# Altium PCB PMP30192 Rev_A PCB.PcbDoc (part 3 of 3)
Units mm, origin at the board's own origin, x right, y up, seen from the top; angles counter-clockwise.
Board outline 142.24 x 157.48 mm, 4 copper layers (Top Layer, Signal Layer 1, Signal Layer 2, Bottom Layer), stack 1.647 mm thick; 198 components, 99 nets, 479 pads, 192 vias.
Unrouted connection lines stored in the file: 2.
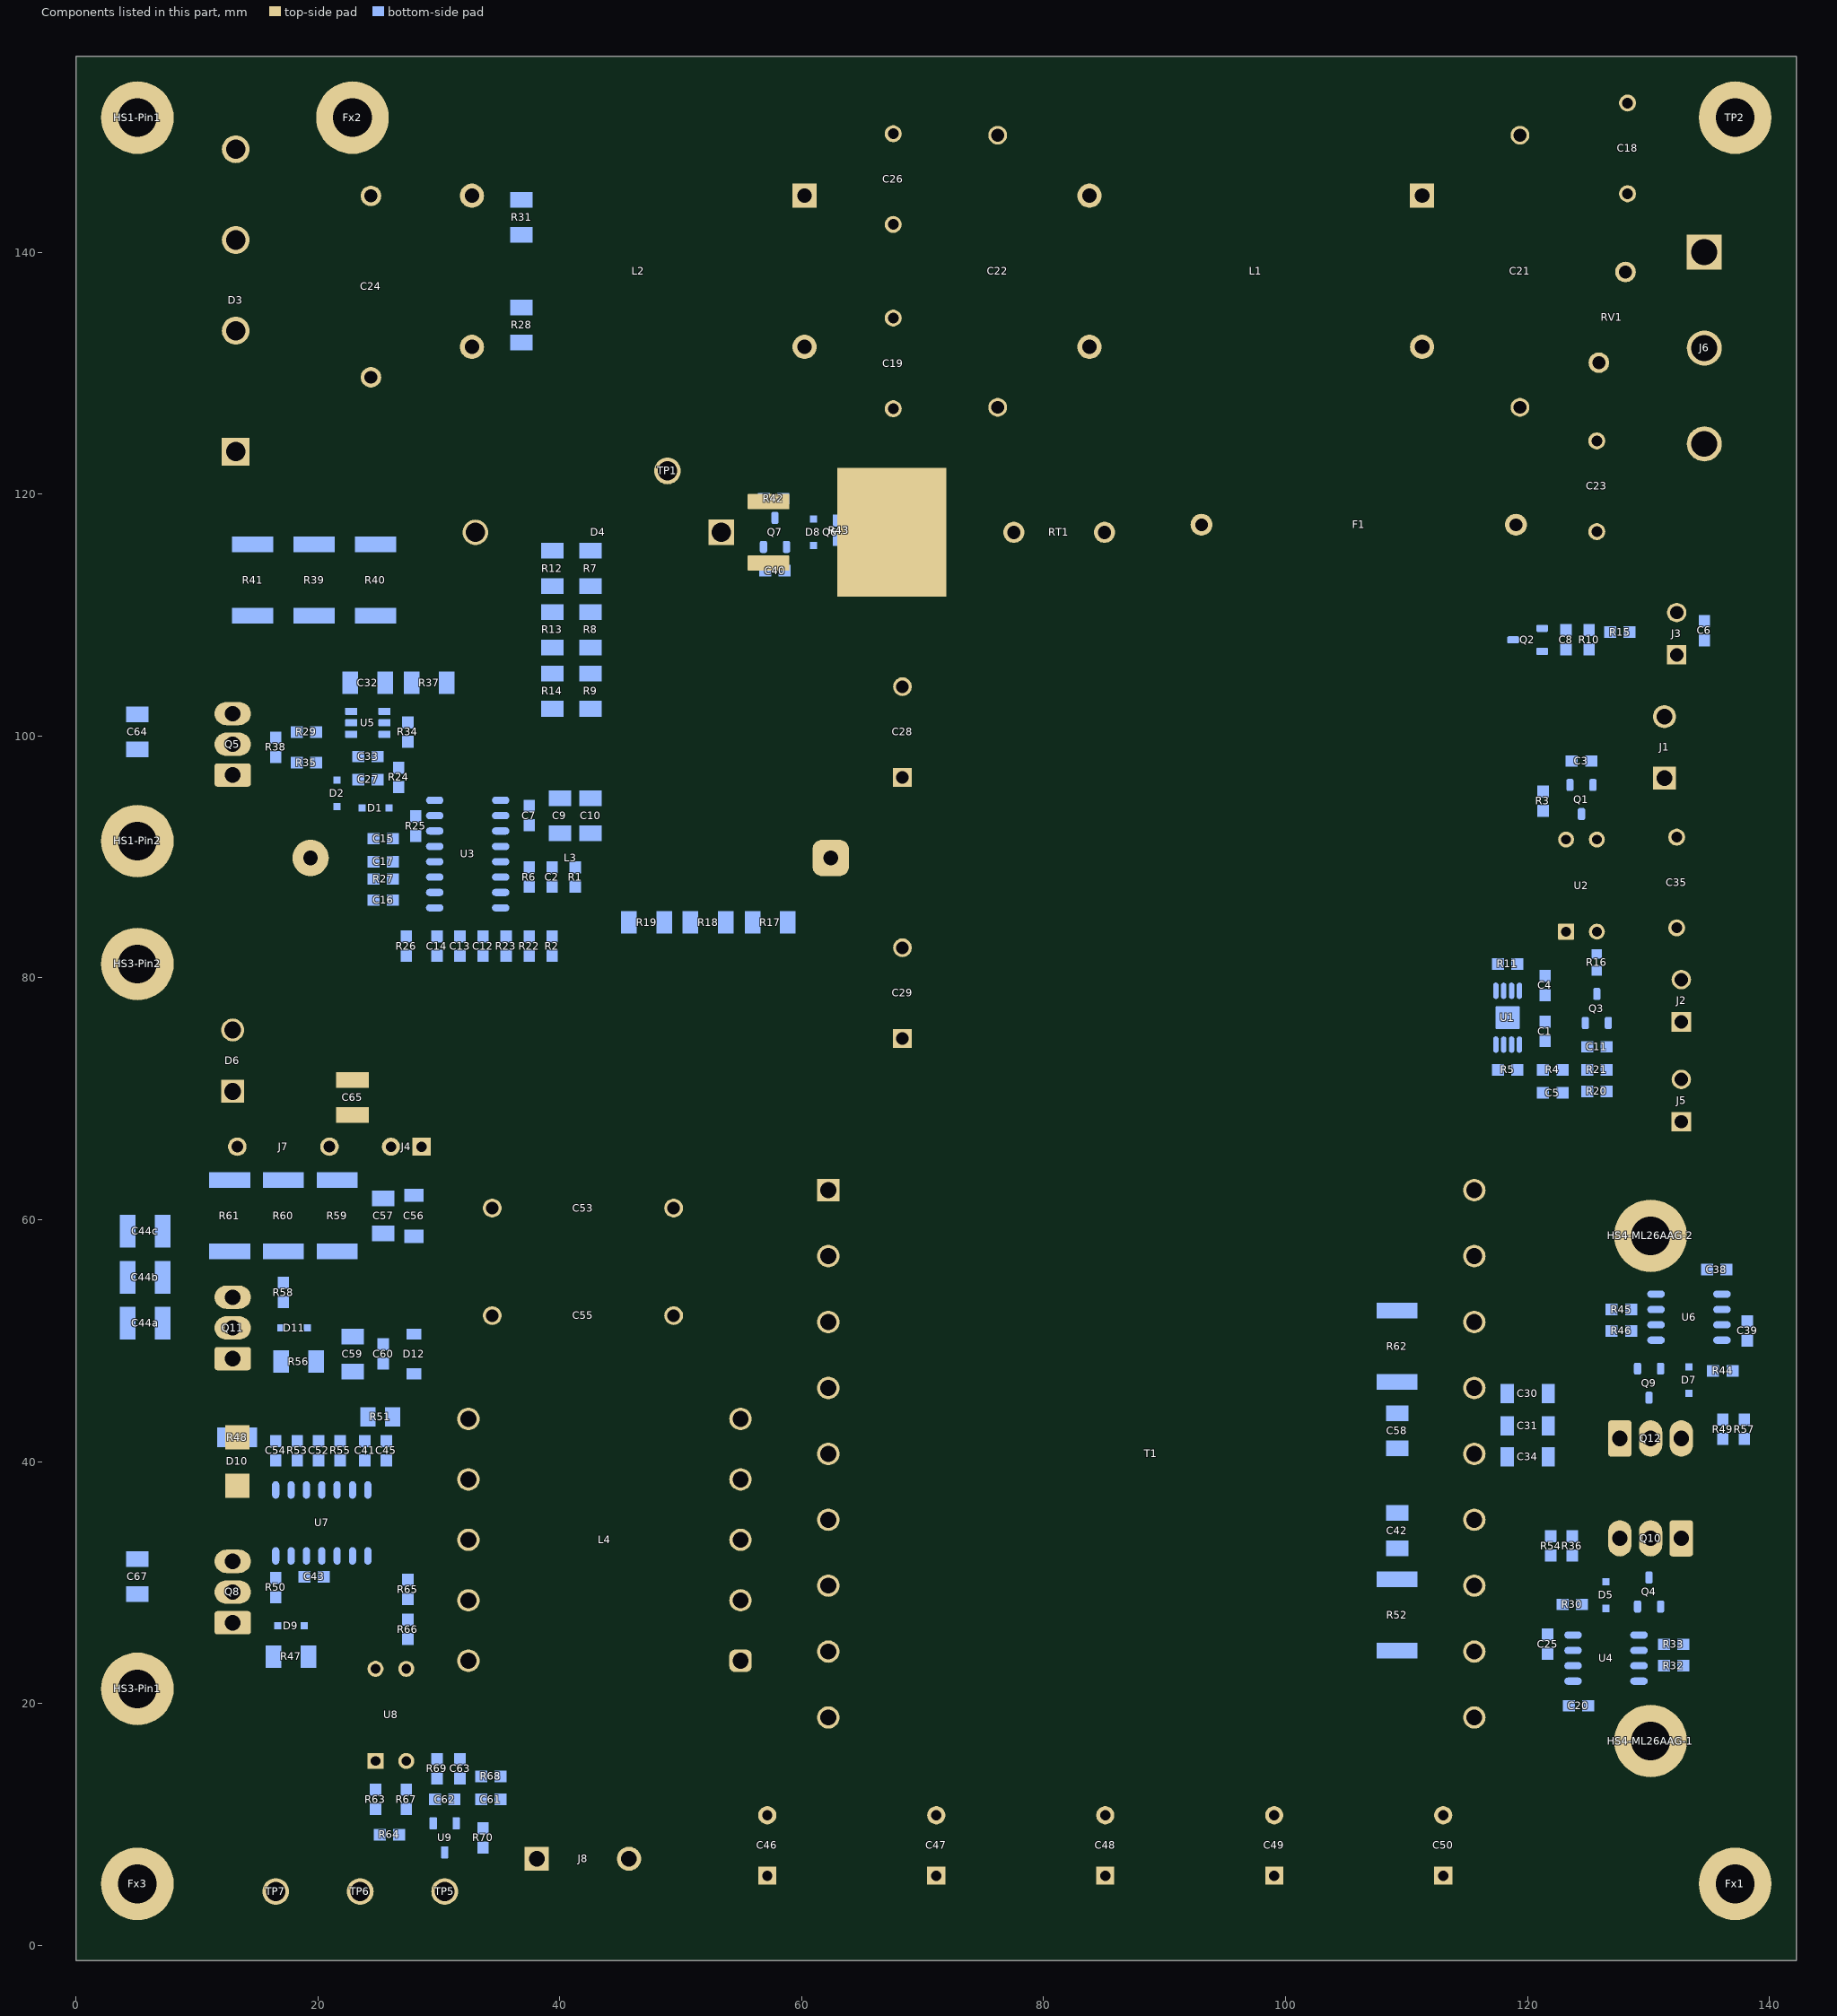
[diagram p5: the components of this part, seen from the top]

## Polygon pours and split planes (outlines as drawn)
SGND on Top Layer "TOP_LAYER_SGND_P070" (solid, remove dead copper, pour order 70): 115.062,78.232 115.062,69.469 124.98,69.469 124.98,76.445 124.438,76.987 121.691,76.987 120.447,78.232
PGND on Top Layer "Top Layer-No Net 8" (solid, pour order 66): 54.61,114.935 61.595,114.935 61.595,104.775 60.96,104.14 55.245,104.14 53.34,106.045 53.34,107.95 53.34,113.665
NetL4_2 on Top Layer "Top Layer-No Net 4" (solid, pour order 34): 52.07,31.242 54.102,32.766 62.23,32.766 64.77,30.226 64.77,22.86 64.135,22.225 57.404,22.225 52.07,25.4
NetC28_2 on Top Layer "Top Layer-No Net 3" (solid, pour order 32): 62.992,122.174 79.756,122.174 81.28,120.65 81.28,112.776 79.756,111.252 62.992,111.252
NetC43_2 on Top Layer "Top Layer-No Net 2" (solid, pour order 30): 1.27,52.462 2.402,53.594 13.716,53.594 16.002,55.88 22.606,55.88 24.892,58.166 51.054,58.166 52.324,59.436 60.452,59.436 62.738,59.436 64.262,57.912 64.262,50.8 61.722,48.26 33.02,48.26 28.956,52.324 22.86,52.324 20.066,52.324 17.526,49.784 14.732,49.784 14.478,49.53 10.668,49.53 10.668,36.068 13.208,33.528 14.986,33.528 15.24,33.528 15.24,30.48 14.986,30.226 14.478,30.226 4.064,30.226 1.27,33.02
BULK on Top Layer "Top Layer-No Net 1" (solid, pour order 28): 9.398,72.136 14.986,72.136 20.828,77.978 41.529,77.978 43.815,81.915 63.099,81.915 65.786,84.602 65.786,98.044 67.31,99.568 72.898,99.568 74.422,98.044 74.422,77.978 74.422,75.692 74.422,72.644 67.818,66.04 36.195,66.04 32.385,66.04 29.083,69.723 20.447,69.723 20.447,66.675 22.225,66.675 22.225,63.5 17.707,63.5 15.24,67.818 9.398,67.818
NetC18_1 on Top Layer "Top Layer-No Net" (solid, pour order 4): 107.95,137.795 107.95,130.175 112.395,125.73 122.663,125.73 134.62,135.89 139.065,135.89 139.065,137.16 139.065,137.795 139.065,144.78 137.795,146.05 133.35,146.05 130.81,148.59 128.27,148.59 125.095,148.59 116.205,139.7 113.03,139.7 109.855,139.7
NetC24_1 on Top Layer "Bottom Layer-No Net 5" (solid, pour order 24): 4.445,137.16 29.21,137.16 48.895,116.84 48.895,104.775 59.055,94.615 64.516,94.615 64.516,85.09 62.992,83.566 48.006,83.566 13.462,118.11 4.445,118.11
NetD6_2 on Top Layer "Signal Layer 1-No Net" (solid, pour order 26): 5.715,100.33 17.78,100.33 17.78,94.806 20.193,92.393 21.59,90.995 21.59,88.004 17.78,84.996 17.78,79.375 17.78,76.2 14.605,73.025 5.715,73.025
VD_SR1 on Top Layer "Top Layer-No Net 5" (solid, pour order 38): 113.284,63.754 114.046,64.516 136.398,64.516 137.668,63.246 137.668,50.8 131.318,44.45 131.318,40.894 130.81,40.386 129.569,40.386 129.54,40.415 129.54,40.64 129.032,41.148 129.032,44.557 129.032,44.704 119.634,54.102 114.154,54.102 113.284,54.972
VD_SR2 on Top Layer "Top Layer-No Net 5" (solid, pour order 44): 112.972,16.198 116.902,12.065 137.541,12.065 137.541,24.511 131.191,30.861 131.191,34.417 130.683,34.925 129.442,34.925 129.413,34.896 129.413,34.671 128.905,34.163 128.905,30.754 128.905,30.607 124.333,26.035 114.3,26.035 112.972,24.707
29V on Top Layer "Top Layer-No Net 6" (solid, pour order 54): 41.275,14.605 77.474,14.605 77.609,14.74 77.609,14.744 91.44,28.575 91.44,49.53 96.52,54.61 112.195,54.61 113.665,53.14 119.58,53.14 121.285,51.435 125.73,46.99 125.73,40.005 125.73,28.575 123.825,26.67 113.665,26.67 112.395,25.4 112.395,15.875 112.395,15.24 116.205,11.43 116.205,0 115.57,-0.635 41.275,-0.635 40.64,0 40.64,13.97
PGND on Top Layer "Top Layer-No Net 9" (solid, pour order 6): 21.59,69.215 27.305,69.215 27.305,64.135 24.765,64.135 23.495,65.405 23.495,66.675 22.225,67.945 21.59,67.945
PFCCS on Bottom Layer "Bottom Layer-No Net 4" (solid, pour order 22): 10.16,154.305 30.48,154.305 30.48,122.555 30.48,120.65 27.94,118.11 27.94,113.665 5.715,113.665 4.445,114.935 4.445,115.57 4.445,144.78 10.16,150.495 10.16,151.13
NetC23_2 on Bottom Layer "Bottom Layer-No Net" (solid, pour order 8): 116.84,121.92 127,121.92 133.35,128.27 135.89,128.27 137.16,128.27 138.43,128.27 138.43,118.11 135.89,115.57 134.62,114.3 123.19,114.3 116.84,114.3
NetC21_2 on Bottom Layer "Bottom Layer-No Net 1" (solid, pour order 10): 107.95,153.67 121.92,153.67 124.77,150.82 124.77,144.59 127.12,142.24 129.54,142.24 130.81,140.97 130.81,135.89 128.27,133.35 124.46,133.35 121.92,133.35 115.57,127 113.03,124.46 113.03,114.825 112.505,114.3 92.71,114.3 91.44,115.57 91.44,121.92 105.41,135.89 105.41,151.13
NetC22_2 on Bottom Layer "Bottom Layer-No Net 2" (solid, pour order 14): 55.88,153.67 88.9,153.67 88.9,139.7 55.88,139.7
NetC19_1 on Bottom Layer "Bottom Layer-No Net 2" (solid, pour order 16): 55.677,138.541 88.697,138.541 88.697,123.301 55.677,123.301
VD_SR1 on Bottom Layer "Bottom Layer-No Net 6" (solid, pour order 40): 104.775,64.77 117.27,64.77 117.9,64.14 117.9,56.305 111.125,49.53 104.775,49.53 104.14,50.165 104.14,64.135
VD_SR2 on Bottom Layer "Bottom Layer-No Net 6" (solid, pour order 42): 104.14,26.67 104.772,27.302 114.938,27.302 117.472,24.768 117.472,17.145 116.68,16.48 104.805,16.48 104.14,17.145
NetC58_2 on Bottom Layer "Bottom Layer-No Net 7" (solid, pour order 46): 104.14,48.895 111.9,48.895 111.9,42.545 104.14,42.545
NetC42_2 on Bottom Layer "Bottom Layer-No Net 7" (solid, pour order 48): 103.935,34.119 111.9,34.119 111.9,27.769 103.935,27.769
29V on Bottom Layer "Bottom Layer-No Net 8" (solid, pour order 50): 112.395,49.53 112.395,50.165 116.205,53.975 118.11,53.975 119.38,52.705 120.015,52.07 120.015,32.385 118.11,30.48 117.475,29.845 117.475,28.575 116.84,27.94 113.1,27.94 112.9,28.14 112.83,28.14 112.395,28.575 112.395,50.165
SGND on Bottom Layer "Bottom Layer-No Net 7" (solid, pour order 52): 104.14,42.105 111.76,42.105 111.76,34.544 104.14,34.544
SGND on Bottom Layer "Top Layer-No Net 7" (solid, pour order 56): 92.075,84.455 139.7,84.455 140.97,83.185 140.97,0.635 140.97,0 140.335,-0.635 13.97,-0.635 12.7,0.635 12.7,13.97 13.97,15.24 14.605,15.875 78.74,15.875 79.375,16.51 91.44,28.575 91.44,83.82 92.075,84.455
PGND on Bottom Layer "Bottom Layer-No Net 9" (solid, pour order 60): 1.27,113.03 41.275,113.03 41.91,113.03 50.165,121.285 88.9,121.285 88.78,121.165 88.78,114.3 91.32,111.76 92.71,111.76 140.335,111.76 140.97,111.125 140.97,92.71 139.7,91.44 118.11,91.44 117.475,91.44 115.57,93.345 114.105,93.345 83.185,93.345 78.74,93.345 74.295,88.9 74.295,33.02 63.5,22.225 1.905,22.225 1.27,22.86
LLC_RCS on Bottom Layer "Bottom Layer-No Net 10" (solid, pour order 0): 6.985,59.69 7.62,60.325 29.845,60.325 33.02,63.5 35.56,63.5 36.83,62.23 36.83,50.165 36.195,49.53 35.56,49.53 32.385,49.53 27.305,54.61 27.219,54.524 16.671,54.524 16.585,54.61 15.24,54.61 14.605,53.975 14.449,53.819 14.449,53.34 14.479,53.31 14.479,52.881 14.302,52.705 13.97,52.705 13.918,52.757 11.403,52.757 10.16,51.514 10.16,48.895 9.525,48.26 6.35,48.26 5.715,48.895 5.715,59.69
NetC44a_2 on Bottom Layer "Bottom Layer-No Net 11" (solid, pour order 2): 1.27,60.96 5.068,60.96 5.068,49.53 1.27,49.53
AC2 on Signal Layer 2 "Bottom Layer-No Net 3" (solid, pour order 18): 10.16,154.305 40.64,154.305 40.64,148.59 40.64,137.795 10.16,137.795
AC1 on Signal Layer 2 "Bottom Layer-No Net 3" (solid, pour order 20): 10.16,120.65 40.64,120.65 40.64,136.525 10.16,136.525
GND on Signal Layer 2 "Signal Layer 2-No Net" (solid, pour order 12): 63.5,154.94 139.7,154.94 140.97,153.67 140.97,115.57 139.7,114.3 100.33,114.3 91.44,123.19 81.28,123.19 63.5,123.19
SGND on Signal Layer 2 "Top Layer-No Net 7" (solid, pour order 58): 92.075,84.455 139.7,84.455 140.97,83.185 140.97,0.635 140.97,0 140.335,-0.635 13.97,-0.635 12.7,0.635 12.7,13.97 13.97,15.24 14.605,15.875 78.74,15.875 79.375,16.51 91.44,28.575 91.44,83.82 92.075,84.455
PGND on Signal Layer 2 "Bottom Layer-No Net 9" (solid, pour order 62): 1.27,113.03 41.275,113.03 41.91,113.03 50.165,121.285 88.9,121.285 88.78,121.165 88.78,114.3 91.32,111.76 92.71,111.76 140.335,111.76 140.97,111.125 140.97,92.71 139.7,91.44 118.11,91.44 117.475,91.44 115.57,93.345 114.105,93.345 83.185,93.345 78.74,93.345 74.295,88.9 74.295,33.02 63.5,22.225 1.905,22.225 1.27,22.86
NetC53_1 on Signal Layer 1 "Signal Layer 1-No Net 1" (solid, pour order 36): 43.688,64.008 45.212,65.532 46.736,65.532 53.34,65.532 54.864,64.008 54.864,50.292 56.642,48.514 56.642,37.084 55.626,36.068 47.752,36.068 46.736,37.084 46.736,47.498 43.688,50.546
NetC28_2 on Signal Layer 1 "Signal Layer 1-No Net 2" (solid, pour order 64): 62.992,120.65 74.295,120.65 74.93,120.015 74.93,119.38 74.93,114.935 81.28,108.585 81.28,104.14 81.28,93.345 69.215,81.28 67.945,81.28 60.96,81.28 55.245,86.995 55.245,91.44 55.245,96.52 62.827,104.102
NetC44a_2 on Signal Layer 1 "Signal Layer 1-No Net 3" (solid, pour order 68): 1.27,67.945 14.605,67.945 15.24,67.31 15.24,63.5 10.16,63.5 10.16,31.115 9.779,31.496 10.16,31.115 13.97,31.115 15.24,29.845 15.24,27.94 14.605,27.305 10.795,27.305 1.27,27.305

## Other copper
Top Layer:
  text ".Layer_Name" at 154.94,93.345 h1.52
Bottom Layer:
  text ".Layer_Name" at 154.94,88.265 h1.52

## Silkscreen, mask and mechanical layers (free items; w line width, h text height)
Top Overlay:
  lines w0.254: 70.866,74.676 68.326,74.676 68.326,75.184 70.866,75.184 ; 70.866,82.296 68.326,82.296 68.326,82.804 70.866,82.804 ; 70.866,96.266 68.326,96.266 68.326,96.774 70.866,96.774 ; 70.866,103.886 68.326,103.886 68.326,104.394 70.866,104.394 ; 70.866,69.596 116.078,69.596 116.078,87.884 70.866,87.884 70.866,69.596 ; 70.866,91.186 70.866,109.474 116.078,109.474 116.078,91.186 70.866,91.186
  lines w0.508: 137.922,132.08 139.7,132.08 ; 139.7,131.318 141.224,129.794 ; 139.7,132.842 141.224,131.318 ; 141.224,128.27 139.7,129.794 139.7,134.366 141.224,132.842
  text "~" at 143.51,135.636 h5.08 r60.95
  text "~" at 143.51,119.634 h5.08 r60.95
  text "GND" at 138.176,109.982 h1.52 r90
  text "Pri." at 140.716,109.982 h1.52 r90
  text "In" at 140.716,105.41 h1.52 r90
  text "14V" at 138.176,104.902 h1.52 r90
  text "GND" at 138.176,99.568 h1.52 r90
  text "Pri." at 140.716,99.568 h1.52 r90
  text "+385V" at 139.192,91.44 h1.52 r90
  text "GND" at 138.43,78.994 h1.52 r90
  text "Sec." at 140.716,78.74 h1.52 r90
  text "7V" at 138.43,75.184 h1.52 r90
  text "In" at 140.716,75.184 h1.52 r90
  text "GND" at 138.176,69.088 h1.52 r90
  text "Sec." at 140.716,68.834 h1.52 r90
  text "EN" at 139.446,65.024 h1.52 r90
  text "'.PRJ_Number'.PCB_Rev-" at 118.364,0.762 h2.75
  text "GND" at 35.306,-0.254 h1.52
  text "Vout" at 43.18,-0.508 h2.03
  text ".Layer_Name" at 14.656,-21.806 h1.52
Bottom Overlay:
  text ".Layer_Name" at 14.656,-21.806 h1.52
Top Solder:
  rectangle: 116.855,75.384 119.518,77.978
Drill Guide:
  text ".Layer_Name" at 154.94,74.93 h1.52
M1 Board Outline:
  the board outline again, w0.254
  text ".Layer_Name" at 154.94,84.455 h1.52
M2 Board Dimensions:
  rectangle: 3.175,-10.16 12.7,-6.985
  rectangle: 0,-6.985 3.175,-3.81
  lines w0.178: 0,-6.985 25.4,-6.985 ; 3.175,-10.16 3.175,-3.81 ; 6.35,-10.16 6.35,-3.81 ; 12.7,-10.16 12.7,-3.81 ; 19.05,-10.16 19.05,-3.81 ; 0,-10.16 0,-3.81 25.4,-3.81 25.4,-10.16 0,-10.16
  lines w0.5: -7.112,40.132 12.192,40.132 ; -6.858,112.776 12.446,112.776 ; -1.778,29.21 17.526,29.21 ; -1.778,147.574 17.526,147.574 ; -1.27,51.054 18.034,51.054 ; -0.254,99.314 19.05,99.314 ; 0.635,68.834 19.939,68.834 ; 7.366,73.152 17.526,73.152 ; 7.874,143.002 7.874,152.126 ; 9.398,135.89 17.526,135.89
  text ".Layer_Name" at 154.94,80.645 h1.52
M5 Assembly Top:
  lines w0.254: -7.417,-23.626 160.223,-23.626 ; -7.417,-18.462 160.274,-18.462 ; -7.417,-13.297 -7.417,-28.791 94.31,-28.791 160.274,-28.791 160.274,-13.297 -7.404,-13.297 -7.404,-28.791 32.614,-28.791 ; 55.194,-28.791 55.194,-13.297 ; 70.866,74.676 68.326,74.676 68.326,75.184 70.866,75.184 ; 70.866,82.296 68.326,82.296 68.326,82.804 70.866,82.804 ; 70.866,96.266 68.326,96.266 68.326,96.774 70.866,96.774 ; 70.866,103.886 68.326,103.886 68.326,104.394 70.866,104.394 ; 87.376,-18.462 87.376,-13.297 ; 108.712,-18.462 108.712,-13.297 ; 124.511,-28.956 124.511,-23.804 ; 5.08,16.193 5.08,16.192 ; 70.866,69.596 70.866,87.884 116.078,87.884 116.078,69.596 70.866,69.596 ; 70.866,91.186 116.078,91.186 116.078,109.474 70.866,109.474 70.866,91.186 ; 122.682,11.049 137.668,11.049 137.668,36.449 135.636,36.449 135.636,30.353 124.714,30.353 124.714,36.449 122.682,36.449 122.682,11.049 ; 122.682,39.116 124.714,39.116 124.714,45.212 135.636,45.212 135.636,39.116 137.668,39.116 137.668,64.516 122.682,64.516 122.682,39.116
  text "COMPONENTS MARKED 'DNP' SHOULD NOT BE POPULATED." at 29.299,-8.09 h1.52
  text "ASSEMBLY VARIANT:" at 29.286,-11.024 h1.52
  text ".VariantName" at 55.601,-11.024 h1.52
  text "BOARD #:" at 57.099,-16.654 h1.52
  text ".PRJ_Number" at 70.955,-16.654 h1.52
  text "REV:" at 92.405,-16.654 h1.52
  text ".PCB_Rev" at 99.809,-16.654 h1.52
  text "SVN REV:" at 113.69,-16.654 h1.52
  text ".VersionControl_RevNumber" at 126.543,-16.654 h1.52
  text "TID #:" at 57.099,-21.819 h1.52
  text ".TID" at 70.955,-21.819 h1.52
  text "PLOT NAME =" at -5.804,-27.034 h1.52
  text ".plot_File_Name" at 14.656,-27.034 h1.52
  text "GENERATED    :" at 57.15,-27.034 h1.52
  text ".Print_Date" at 79.235,-27.034 h1.52
  text ".Print_Time" at 97.752,-27.034 h1.52
  text "TEXAS INSTRUMENTS" at 129.87,-27.034 h1.52
M6 Assembly Bottom:
  lines w0.254: -7.429,-18.474 160.261,-18.474 ; -7.379,-23.639 160.261,-23.639 ; 28.334,-28.969 28.334,-23.817 ; 44.133,-18.474 44.133,-13.31 ; 65.468,-18.474 65.468,-13.31 ; 97.65,-28.804 97.65,-13.31 ; 120.231,-28.804 160.249,-28.804 160.249,-13.31 -7.429,-13.31 -7.429,-28.804 58.534,-28.804 160.261,-28.804 160.261,-13.31
  text "COMPONENTS MARKED 'DNP' SHOULD NOT BE POPULATED." at 154.991,-8.077 h1.52
  text ".VariantName" at 128.473,-11.024 h1.52
  text "ASSEMBLY VARIANT:" at 154.864,-11.024 h1.52
  text ".VersionControl_RevNumber" at 26.302,-16.667 h1.52
  text "SVN REV:" at 39.154,-16.667 h1.52
  text ".PCB_Rev" at 53.035,-16.667 h1.52
  text "REV:" at 60.439,-16.667 h1.52
  text ".PRJ_Number" at 81.89,-16.667 h1.52
  text "BOARD #:" at 95.745,-16.667 h1.52
  text "PCB VIEWED FROM BOTTOM SIDE" at 158.648,-16.667 h1.52
  text ".TID" at 81.89,-21.831 h1.52
  text "TID #:" at 95.745,-21.831 h1.52
  text "TEXAS INSTRUMENTS" at 22.974,-27.047 h1.52
  text ".Print_Time" at 55.093,-27.047 h1.52
  text ".Print_Date" at 73.609,-27.047 h1.52
  text "GENERATED    :" at 95.694,-27.047 h1.52
  text ".plot_File_Name" at 138.189,-27.047 h1.52
  text "PLOT NAME =" at 158.648,-27.047 h1.52
M9 Title Sheet:
  drawing of 57 lines, arcs and shapes, not listed
  text "1" at 18.792,204.127 h1.78
  text "2" at 82.182,204.127 h1.78
  text "3" at 145.411,204.127 h1.78
  text "4" at 209.08,204.127 h1.78
  text "5" at 272.555,204.127 h1.78
  text "6" at 336.182,204.127 h1.78
  text "A" at -10.579,175.095 h1.78
  text "A" at 365.341,175.095 h1.78
  text "B" at -10.579,114.643 h1.78
  text "B" at 365.341,114.643 h1.78
  text "C" at -10.579,54.318 h1.78
  text "C" at 365.341,54.318 h1.78
  text "PROJECT TITLE:" at 288.125,7.048 h1.14
  text ".PRJ_Title" at 289.395,3.662 h1.78
  text "DESIGNED FOR:" at 288.125,-0.597 h1.14
  text ".PRJ_Customer" at 289.395,-4.153 h1.78
  text "D" at -10.579,-5.88 h1.78
  text "D" at 365.341,-5.88 h1.78
  text "FILE NAME:" at 288.125,-8.217 h1.14
  text ".PCB_File_Name_No_Path" at 289.395,-11.265 h1.78
  text "Texas Instruments (TI) and/or its licensors do not warrant the accuracy or completeness of this specification" at 161.9,-15.376 h1.14
  text "ENGINEER:" at 288.125,-15.583 h1.14
  text "LAYOUT BY:" at 326.352,-15.583 h1.14
  text "or any information contained therein. TI and/or its licensors do not warrant that this design will meet" at 160.757,-18.237 h1.14
  text ".PRJ_Engineer" at 289.395,-19.52 h1.78
  text ".PCB_Layout" at 327.635,-19.52 h1.78
  text "the specifications, will be suitable for your application or fit for any particular purpose, or will operate in" at 160.757,-21.099 h1.14
  text "ALTIUM DESIGNER VERSION:" at 326.352,-23.457 h1.14
  text "an implementation. TI and/or its licensors do not warrant that the design is production worthy. You should" at 160.757,-23.961 h1.14
  text "completely validate and test your design implementation to confirm the system functionality for your application." at 161.9,-26.822 h1.14
  text ".print_Scale" at 289.395,-26.843 h1.78
  text ".Application_BuildNumber" at 327.635,-26.843 h1.78
  text "1" at 18.792,-32.093 h1.78
  text "2" at 82.182,-32.093 h1.78
  text "3" at 145.411,-32.093 h1.78
  text "4" at 209.08,-32.093 h1.78
  text "5" at 272.555,-32.093 h1.78
  text "6" at 336.182,-32.093 h1.78
M10 Fab Notes:
  drawing of 173 lines, arcs and shapes, not listed
  text "DESIGN INFORMATION" at 314.402,157.505 h1.52
  text "MIN. TRACK WIDTH:" at 298.03,152.933 h1.52
  text "8" at 325.874,152.933 h1.52
  text "MIL" at 329.805,152.933 h1.52
  text "MIN. CLEARANCE:" at 298.03,149.581 h1.52
  text "0.2" at 324.35,149.581 h1.52
  text "mm" at 329.805,149.581 h1.52
  text "MIN. VIA PAD SIZE:" at 298.03,146.228 h1.52
  text "24" at 325.113,146.228 h1.52
  text "MIL" at 329.805,146.228 h1.52
  text "0.05mm (2MIL)" at 315.683,142.628 h1.52
  text "MINIMUM ANNULAR RING" at 289.667,142.52 h1.52
  text "EXTERNAL" at 333.666,142.52 h1.52
  text "PER" at 294.747,139.522 h1.52
  text "IPC-D-275 CLASS 2 LEVEL C" at 300.335,139.522 h1.52
  text "MIL, HOLES" at 338.136,136.67 h1.52
  text "+/-" at 328.168,136.652 h1.52
  text "+/-" at 349.86,136.652 h1.52
  text "REGISTRATION TOLERANCES:" at 289.667,136.525 h1.52
  text "METAL" at 320.142,136.525 h1.52
  text "5" at 334.777,136.525 h1.52
  text "3" at 355.935,136.525 h1.52
  text "MIL" at 358.888,136.525 h1.52
  text "+/-" at 349.86,133.655 h1.52
  text "HOLE SIZE TOLERANCE (UNLESS OTHERWISE SPECIFIED):" at 289.667,133.528 h1.52
  text "3" at 355.935,133.528 h1.52
  text "MIL" at 358.888,133.528 h1.52
  text "MATERIAL:" at 287.768,128.208 h1.52
  text "FR-4 High Tg" at 312.824,124.643 h1.52
  text "FR-408" at 298.462,124.425 h1.52
  text "OTHER" at 336.257,124.425 h1.52
  text "X" at 308.889,124.333 h1.52
  text "62 MIL (1.6mm) +/-10%" at 306.592,120.292 h1.52
  text "THICKNESS:" at 289.667,120.184 h1.52
  text "X" at 303.337,120.184 h1.52
  text "OTHER" at 339.229,120.184 h1.52
  text "TOLERANCE:" at 289.667,116.17 h1.52
  text "X" at 310.986,116.17 h1.52
  text "ANSI IPC-6012 TYPE 3 CLASS 2" at 315.734,116.17 h1.52
  text "OTHER +/-" at 315.734,112.208 h1.52
  text "BOW & TWIST:" at 289.667,108.22 h1.52
  text "X" at 310.986,108.22 h1.52
  text "ANSI IPC-6012 TYPE 3 CLASS 2" at 315.734,108.22 h1.52
  text "OTHER +/-" at 315.734,104.194 h1.52
  text "DRILLING:" at 287.768,100.676 h1.52
  text "REFERENCE:" at 289.667,97.705 h1.52
  text "X" at 306.132,97.705 h1.52
  text "AS SHOWN" at 310.882,97.705 h1.52
  text "X" at 329.018,97.705 h1.52
  text "NC_DRILL FILES" at 332.498,97.705 h1.52
  text "PTH COPPER THICKNESS:" at 289.667,93.691 h1.52
  text "X" at 318.375,93.691 h1.52
  text "20-30 um" at 321.855,93.691 h1.52
  text "OTHER" at 340.067,93.691 h1.52
  text "BOARD FINISH:" at 287.768,89.653 h1.52
  text "SILKSCREEN:" at 291.711,86.656 h1.52
  text "X" at 315.81,86.656 h1.52
  text "TOP" at 319.01,86.656 h1.52
  text "X" at 328.764,86.656 h1.52
  text "BOTTOM" at 331.99,86.656 h1.52
  text "SILKSCREEN COLOR:" at 291.711,82.414 h1.52
  text "X" at 315.783,82.414 h1.52
  text "WHITE" at 319.01,82.414 h1.52
  text "OTHER" at 331.99,82.414 h1.52
  text "X" at 319.111,78.37 h1.52
  text "GREEN" at 322.338,78.37 h1.52
  text "OTHER" at 338.035,78.37 h1.52
  text "SOLDER RESIST COLOR:" at 291.711,78.096 h1.52
  text "X" at 319.111,74.052 h1.52
  text "MATTE" at 322.338,74.052 h1.52
  text "SEMI-GLOSS" at 338.023,74.036 h1.52
  text "IMMERSION GOLD (ENIG)" at 314.718,69.264 h1.52
  text "ENEPIG" at 348.691,69.18 h1.52
  text "SURFACE FINISH:" at 287.768,69.155 h1.52
  text "X" at 309.969,69.155 h1.52
  text "IMM. TIN/SILVER OR EQUIV" at 296.139,65.167 h1.52
  text "OTHER" at 332.498,65.167 h1.52
  text "ARRAY/PANEL:" at 287.768,60.621 h1.52
  text "CUT AND TRIM PER M1 BOARD OUTLINE" at 314.718,60.512 h1.52
  text "N.C. ROUTE" at 314.718,56.658 h1.52
  text "X" at 331.964,56.658 h1.52
  text "V. SCORE" at 336.714,56.658 h1.52
  text "CERTIFICATION:" at 287.768,53.178 h1.52
  text "MATERIALS AND WORKMANSHIP FOR ALL PCBS" at 306.183,53.178 h1.52
  text "TO MEET OR EXCEED THE REQUIREMENTS OF:" at 306.183,50.689 h1.52
  text "X" at 296.696,47.222 h1.52
  text "ANSI IPC-A-600F CLASS ->" at 300.227,47.222 h1.52
  text "X" at 341.859,47.222 h1.52
  text "2" at 344.88,47.222 h1.52
  text "1" at 336.879,47.184 h1.52
  text "3" at 353.872,47.184 h1.52
  text "X" at 317.373,43.171 h1.52
  text "RoHS" at 320.852,43.171 h1.52
  text "OTHER" at 337.22,43.171 h1.52
  text "PER ORDER" at 347.305,43.171 h1.52
  text "ALL BOARDS MUST MEET OR EXCEED UL94-V0 REQUIREMENTS." at 288.468,38.964 h1.52
  text "PCB MUST BEAR THE UL94V-0 UL REGISTERED MATERIAL ID NUMBER" at 288.468,35.916 h1.52
  text "ADDITIONAL REQUIREMENTS:" at 287.768,31.512 h1.52
  text "MICROSECTION:" at 289.667,28.591 h1.52
  text "YES" at 312.673,28.591 h1.52
  text "REQUIRED" at 334.555,24.625 h1.52
  text "BARE BOARD ELEC. TEST:" at 289.667,24.553 h1.52
  text "NONE" at 322.833,24.553 h1.52
  text "X" at 331.329,24.553 h1.52
  text "PER ORDER" at 349.592,24.553 h1.52
M11 Gerber Information:
  lines w0.254: -7.417,-23.626 160.223,-23.626 ; -7.417,-18.462 160.274,-18.462 ; -7.417,-13.297 -7.417,-28.791 94.31,-28.791 160.274,-28.791 160.274,-13.297 -7.404,-13.297 -7.404,-28.791 32.614,-28.791 ; 55.194,-28.791 55.194,-13.297 ; 87.376,-18.462 87.376,-13.297 ; 108.712,-18.462 108.712,-13.297 ; 124.511,-28.956 124.511,-23.804
  text "BOARD #:" at 57.099,-16.654 h1.52
  text ".PRJ_Number" at 70.955,-16.654 h1.52
  text "REV:" at 92.405,-16.654 h1.52
  text ".PCB_Rev" at 99.809,-16.654 h1.52
  text "SVN REV:" at 113.69,-16.654 h1.52
  text ".VersionControl_RevNumber" at 126.543,-16.654 h1.52
  text "LAYER NAME =" at -5.804,-21.806 h1.52
  text "TID #:" at 57.099,-21.819 h1.52
  text ".TID" at 70.955,-21.819 h1.52
  text "PLOT NAME =" at -5.804,-27.034 h1.52
  text ".plot_File_Name" at 14.656,-27.034 h1.52
  text "GENERATED    :" at 57.15,-27.034 h1.52
  text ".Print_Date" at 79.235,-27.034 h1.52
  text ".Print_Time" at 97.752,-27.034 h1.52
  text "TEXAS INSTRUMENTS" at 129.87,-27.034 h1.52
M12 Stackup:
  drawing of 191 lines, arcs and shapes, not listed
  text "Layer" at 248.675,198.882 h1.52
  text "Name" at 259.086,198.882 h1.52
  text "Material" at 282.702,198.882 h1.52
  text "Thickness" at 304.54,198.882 h1.52
  text "Constant" at 321.046,198.882 h1.52
  text "Board Layer Stack" at 335.52,198.882 h1.52
  text "1" at 248.675,195.834 h1.52
  text "Top Overlay" at 259.086,195.834 h1.52
  text "2" at 248.675,192.786 h1.52
  text "Top Solder" at 259.086,192.786 h1.52
  text "Solder Resist" at 282.702,192.786 h1.52
  text "0.40mil" at 304.54,192.786 h1.52
  text "3.5" at 321.046,192.786 h1.52
  text "3" at 248.675,189.738 h1.52
  text "Top Layer" at 259.086,189.738 h1.52
  text "Copper" at 282.702,189.738 h1.52
  text "1.40mil" at 304.54,189.738 h1.52
  text "4" at 248.675,186.69 h1.52
  text "Dielectric1" at 259.086,186.69 h1.52
  text "FR-4" at 282.702,186.69 h1.52
  text "59.20mil" at 304.54,186.69 h1.52
  text "4.8" at 321.046,186.69 h1.52
  text "5" at 248.675,183.642 h1.52
  text "Bottom Layer" at 259.086,183.642 h1.52
  text "Copper" at 282.702,183.642 h1.52
  text "1.40mil" at 304.54,183.642 h1.52
  text "6" at 248.675,180.594 h1.52
  text "Bottom Solder" at 259.086,180.594 h1.52
  text "Solder Resist" at 282.702,180.594 h1.52
  text "0.40mil" at 304.54,180.594 h1.52
  text "3.5" at 321.046,180.594 h1.52
  text "7" at 248.675,177.546 h1.52
  text "Bottom Overlay" at 259.086,177.546 h1.52
Drill Drawing:
  circle w0.254: c189.309,77.814 r0.422
  circle w0.254: c189.309,77.814 r0.703
  circle w0.254: c189.309,39.879 r0.703
  lines w0.254: 188.607,43.742 190.012,43.742 189.309,42.337 188.607,43.742 ; 188.607,45.499 190.012,45.499 190.012,46.904 188.607,46.904 188.607,45.499 ; 188.607,50.065 190.012,50.065 189.309,48.66 188.607,50.065 ; 188.607,51.821 188.607,52.172 188.958,52.524 188.607,52.875 188.607,53.226 188.958,53.226 189.309,52.875 189.661,53.226 190.012,53.226 190.012,52.875 189.661,52.524 190.012,52.172 190.012,51.821 189.661,51.821 189.309,52.172 188.958,51.821 188.607,51.821 ; 188.607,58.495 188.958,58.495 189.309,58.144 189.661,58.495 190.012,58.495 189.661,58.846 190.012,59.197 189.661,59.197 189.309,59.549 188.958,59.197 188.607,59.197 188.958,58.846 188.607,58.495 ; 188.607,61.305 189.309,61.656 190.012,61.305 189.661,62.007 190.012,62.71 189.309,62.359 188.607,62.71 188.958,62.007 188.607,61.305 ; 188.607,64.466 189.309,64.817 190.012,64.466 189.661,65.169 190.012,65.871 189.309,65.52 188.607,65.871 188.958,65.169 188.607,64.466 ; 188.607,71.14 188.958,71.14 189.309,70.789 189.661,71.14 190.012,71.14 189.661,71.491 190.012,71.842 189.661,71.842 189.309,72.194 188.958,71.842 188.607,71.842 188.958,71.491 188.607,71.14 ; 188.607,80.624 188.958,80.624 188.958,80.272 189.661,80.272 189.661,80.624 190.012,80.624 190.012,81.326 189.661,81.326 189.661,81.677 188.958,81.677 188.958,81.326 188.607,81.326 188.607,80.624 ; 188.607,86.946 188.958,86.946 188.958,86.595 189.661,86.595 189.661,86.946 190.012,86.946 190.012,87.649 189.661,87.649 189.661,88 188.958,88 188.958,87.649 188.607,87.649 188.607,86.946 ; 188.888,43.461 189.731,43.461 189.309,42.618 188.888,43.461 ; 188.888,61.586 189.309,61.797 189.731,61.586 189.52,62.007 189.731,62.429 189.309,62.218 188.888,62.429 189.099,62.007 188.888,61.586 ; 188.888,71.28 189.099,71.28 189.309,71.07 189.52,71.28 189.731,71.28 189.52,71.491 189.731,71.702 189.52,71.702 189.309,71.913 189.099,71.702 188.888,71.702 189.099,71.491 188.888,71.28 ; 188.888,80.764 189.099,80.764 189.099,80.553 189.52,80.553 189.52,80.764 189.731,80.764 189.731,81.186 189.52,81.186 189.52,81.396 189.099,81.396 189.099,81.186 188.888,81.186 188.888,80.764
  lines w0.305: 187.333,38.228 269.445,38.228 ; 187.333,104.614 269.445,104.614 ; 195.923,35.067 195.923,107.775 ; 204.358,35.067 204.358,107.775 ; 220.538,35.067 220.538,107.775 ; 227.126,35.067 227.126,107.775 ; 236.662,35.067 236.662,107.775 ; 255.047,35.067 255.047,107.775 ; 187.333,35.067 269.445,35.067 269.445,107.775 187.333,107.775 187.333,35.067
  text "Symbol" at 189.23,105.562 h1.83
  text "Quantity" at 196.871,105.562 h1.83
  text "Finished Hole Size" at 205.307,105.562 h1.83
  text "Plated" at 221.487,105.562 h1.83
  text "Hole Type" at 228.074,105.562 h1.83
  text "Drill Layer Pair" at 237.61,105.562 h1.83
  text "Hole Tolerance" at 255.996,105.562 h1.83
  text "5" at 196.871,102.401 h1.52
  text "11.81mil (0.300mm)" at 205.307,102.401 h1.52
  text "PTH" at 221.487,102.401 h1.52
  text "Round" at 228.074,102.401 h1.52
  text "Top Layer - Bottom Layer" at 237.61,102.401 h1.52
  text "N" at 188.587,102.147 h1.41
  text "106" at 196.871,99.24 h1.52
  text "19.69mil (0.500mm)" at 205.307,99.24 h1.52
  text "PTH" at 221.487,99.24 h1.52
  text "Round" at 228.074,99.24 h1.52
  text "Top Layer - Bottom Layer" at 237.61,99.24 h1.52
  text "K" at 188.587,98.986 h1.41
  text "81" at 196.871,96.079 h1.52
  text "28.00mil (0.711mm)" at 205.307,96.079 h1.52
  text "PTH" at 221.487,96.079 h1.52
  text "Round" at 228.074,96.079 h1.52
  text "Top Layer - Bottom Layer" at 237.61,96.079 h1.52
  text "J" at 188.587,95.825 h1.41
  text "8" at 196.871,92.917 h1.52
  text "31.50mil (0.800mm)" at 205.307,92.917 h1.52
  text "PTH" at 221.487,92.917 h1.52
  text "Round" at 228.074,92.917 h1.52
  text "Top Layer - Bottom Layer" at 237.61,92.917 h1.52
  text "M" at 188.587,92.664 h1.41
  text "12" at 196.871,89.756 h1.52
  text "33.46mil (0.850mm)" at 205.307,89.756 h1.52
  text "PTH" at 221.487,89.756 h1.52
  text "Round" at 228.074,89.756 h1.52
  text "Top Layer - Bottom Layer" at 237.61,89.756 h1.52
  text "E" at 188.587,89.502 h1.41
  text "10" at 196.871,86.595 h1.52
  text "35.43mil (0.900mm)" at 205.307,86.595 h1.52
  text "PTH" at 221.487,86.595 h1.52
  text "Round" at 228.074,86.595 h1.52
  text "Top Layer - Bottom Layer" at 237.61,86.595 h1.52
  text "2" at 196.871,83.434 h1.52
  text "38.00mil (0.965mm)" at 205.307,83.434 h1.52
  text "PTH" at 221.487,83.434 h1.52
  text "Round" at 228.074,83.434 h1.52
  text "Top Layer - Bottom Layer" at 237.61,83.434 h1.52
  text "A" at 188.587,83.18 h1.41
  text "2" at 196.871,80.272 h1.52
  text "41.00mil (1.041mm)" at 205.307,80.272 h1.52
  text "PTH" at 221.487,80.272 h1.52
  text "Round" at 228.074,80.272 h1.52
  text "Top Layer - Bottom Layer" at 237.61,80.272 h1.52
  text "12" at 196.871,77.111 h1.52
  text "41.34mil (1.050mm)" at 205.307,77.111 h1.52
  text "PTH" at 221.487,77.111 h1.52
  text "Round" at 228.074,77.111 h1.52
  text "Top Layer - Bottom Layer" at 237.61,77.111 h1.52
  text "2" at 196.871,73.95 h1.52
  text "42.00mil (1.067mm)" at 205.307,73.95 h1.52
  text "PTH" at 221.487,73.95 h1.52
  text "Round" at 228.074,73.95 h1.52
  text "Top Layer - Bottom Layer" at 237.61,73.95 h1.52
  text "H" at 188.587,73.696 h1.41
  text "2" at 196.871,70.789 h1.52
  text "42.08mil (1.069mm)" at 205.307,70.789 h1.52
  text "PTH" at 221.487,70.789 h1.52
  text "Round" at 228.074,70.789 h1.52
  text "Top Layer - Bottom Layer" at 237.61,70.789 h1.52
  text "8" at 196.871,67.627 h1.52
  text "43.31mil (1.100mm)" at 205.307,67.627 h1.52
  text "PTH" at 221.487,67.627 h1.52
  text "Round" at 228.074,67.627 h1.52
  text "Top Layer - Bottom Layer" at 237.61,67.627 h1.52
  text "B" at 188.587,67.374 h1.41
  text "10" at 196.871,64.466 h1.52
  text "47.24mil (1.200mm)" at 205.307,64.466 h1.52
  text "PTH" at 221.487,64.466 h1.52
  text "Round" at 228.074,64.466 h1.52
  text "Top Layer - Bottom Layer" at 237.61,64.466 h1.52
  text "15" at 196.871,61.305 h1.52
  text "50.00mil (1.270mm)" at 205.307,61.305 h1.52
  text "PTH" at 221.487,61.305 h1.52
  text "Round" at 228.074,61.305 h1.52
  text "Top Layer - Bottom Layer" at 237.61,61.305 h1.52
  text "4" at 196.871,58.144 h1.52
  text "51.18mil (1.300mm)" at 205.307,58.144 h1.52
  text "PTH" at 221.487,58.144 h1.52
  text "Round" at 228.074,58.144 h1.52
  text "Top Layer - Bottom Layer" at 237.61,58.144 h1.52
  text "28" at 196.871,54.982 h1.52
  text "51.97mil (1.320mm)" at 205.307,54.982 h1.52
  text "PTH" at 221.487,54.982 h1.52
  text "Round" at 228.074,54.982 h1.52
  text "Top Layer - Bottom Layer" at 237.61,54.982 h1.52
  text "D" at 188.587,54.729 h1.41
  text "2" at 196.871,51.821 h1.52
  text "55.12mil (1.400mm)" at 205.307,51.821 h1.52
  text "PTH" at 221.487,51.821 h1.52
  text "Round" at 228.074,51.821 h1.52
  text "Top Layer - Bottom Layer" at 237.61,51.821 h1.52
  text "6" at 196.871,48.66 h1.52
  text "62.99mil (1.600mm)" at 205.307,48.66 h1.52
  text "PTH" at 221.487,48.66 h1.52
  text "Round" at 228.074,48.66 h1.52
  text "Top Layer - Bottom Layer" at 237.61,48.66 h1.52
  text "4" at 196.871,45.499 h1.52
  text "63.00mil (1.600mm)" at 205.307,45.499 h1.52
  text "PTH" at 221.487,45.499 h1.52
  text "Round" at 228.074,45.499 h1.52
  text "Top Layer - Bottom Layer" at 237.61,45.499 h1.52
  text "3" at 196.871,42.337 h1.52
  text "84.65mil (2.150mm)" at 205.307,42.337 h1.52
  text "PTH" at 221.487,42.337 h1.52
  text "Round" at 228.074,42.337 h1.52
  text "Top Layer - Bottom Layer" at 237.61,42.337 h1.52
  text "10" at 196.871,39.176 h1.52
  text "125.98mil (3.200mm)" at 205.307,39.176 h1.52
  text "PTH" at 221.487,39.176 h1.52
  text "Round" at 228.074,39.176 h1.52
  text "Top Layer - Bottom Layer" at 237.61,39.176 h1.52
  text "332 Total" at 196.871,36.015 h1.52
M17 Embedded Cavity:
  text ".Layer_Name" at 14.656,-21.806 h1.52
M18 Embedded Assembly:
  text ".Layer_Name" at 14.656,-21.806 h1.52
M19 Embedded Keepout:
  text ".Layer_Name" at 14.656,-21.806 h1.52

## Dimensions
0,0 to 142.24,-1.27 on M2 Board Dimensions
0,-1.27 to 0,156.21 on M2 Board Dimensions
0,-10.16 to 25.4,-10.16 on M2 Board Dimensions
5.08,151.13 to 0.063,156.21 on M2 Board Dimensions
10.097,156.21 to 13.958,151.067 on M2 Board Dimensions
10.158,151.067 to 17.526,135.89 on M2 Board Dimensions
0.064,86.201 to 5.08,91.313 on M2 Board Dimensions
10.097,86.201 to -0.254,99.314 on M2 Board Dimensions
9.398,135.89 to 5.08,151.13 on M2 Board Dimensions
-1.27,86.201 to 5.08,81.153 on M2 Board Dimensions
5.08,16.192 to 5.08,21.209 on M2 Board Dimensions
-1.27,86.201 to 17.526,73.152 on M2 Board Dimensions
10.097,16.192 to 17.526,29.21 on M2 Board Dimensions
10.097,86.201 to 18.034,51.054 on M2 Board Dimensions
12.446,112.776 to 10.158,120.767 on M2 Board Dimensions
